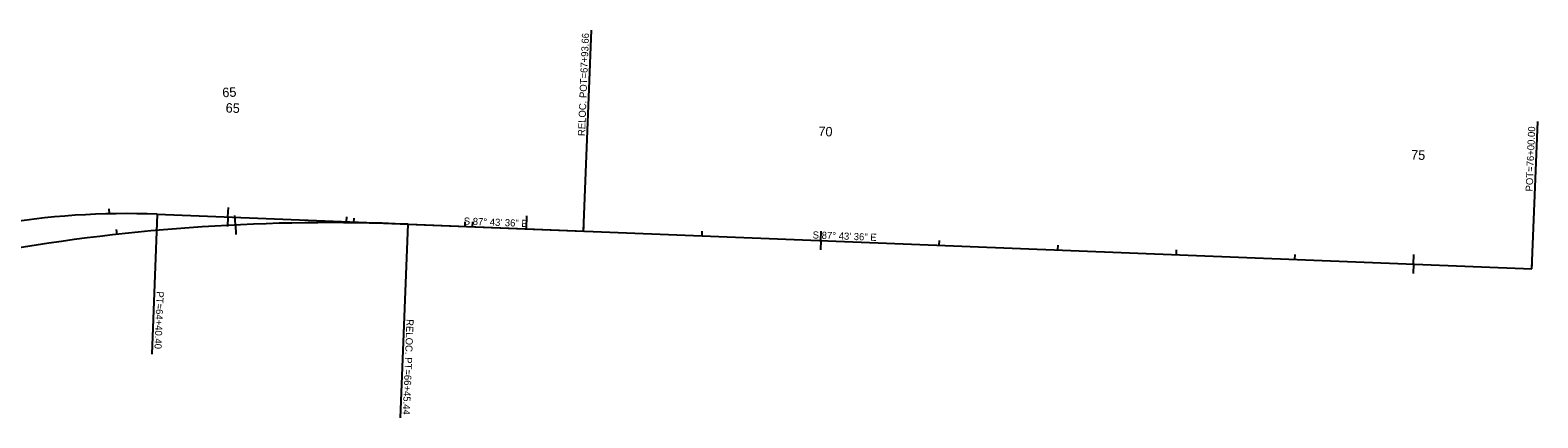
# Model space of a CAD drawing. Extents: x 1966719 to 1969284, y 1117441 to 1118086.
# Drawn here: x 1968013 to 1969284, y 1117759 to 1118086 of the extents above; entities that cross this region are included whole.
import ezdxf

# ---------------------------------------------------------------- set-up
doc = ezdxf.new("R2010")
doc.units = 0
for name, color, linetype in [('Level 1', 7, 'Continuous'), ('Level 19', 7, 'Continuous'), ('Level 21', 7, 'Continuous'), ('Level 39', 7, 'Continuous')]:
    doc.layers.add(name, color=color, linetype=linetype)

msp = doc.modelspace()

# ---------------------------------------------------------------- linework, layer by layer
at = {"layer": 'Level 1'}
for p, q in [((1969279, 1117884.9), (1969283.9, 1118009.1)), ((1968179.9, 1117928.6), (1968180.2, 1117936.6)), ((1968079.9, 1117931.3), (1968079.8, 1117935.3)), ((1968120.3, 1117930.9), (1968115.6, 1117812.9)), ((1968120.3, 1117930.9), (1969279, 1117884.9)), ((1968179.9, 1117928.6), (1968179.6, 1117920.6)), ((1968279.8, 1117924.6), (1968280, 1117928.6)), ((1968379.7, 1117920.6), (1968379.9, 1117924.6)), ((1968479.6, 1117916.7), (1968479.8, 1117920.7)), ((1968579.6, 1117912.7), (1968579.7, 1117916.7)), ((1968679.5, 1117908.7), (1968679.8, 1117916.7)), ((1968679.5, 1117908.7), (1968679.2, 1117900.8)), ((1968779.4, 1117904.8), (1968779.6, 1117908.8)), ((1968879.3, 1117900.8), (1968879.5, 1117904.8)), ((1968979.3, 1117896.8), (1968979.4, 1117900.8)), ((1969079.2, 1117892.9), (1969079.3, 1117896.9)), ((1969179.1, 1117888.9), (1969178.8, 1117880.9)), ((1969179.1, 1117888.9), (1969179.4, 1117896.9)), ((1969279, 1117884.9), (1969279.2, 1117888.9))]:
    msp.add_line(p, q, dxfattribs=at)
msp.add_arc((1968094.4, 1117277.5), 653.9, 87.7266, 111.9958, dxfattribs=at)
at = {"layer": 'Level 19'}
for p, q in [((1968186.2, 1117921.9), (1968185.8, 1117929.9)), ((1968286.1, 1117923.7), (1968286.2, 1117927.7)), ((1968386.1, 1117920.4), (1968386.2, 1117924.4)), ((1968431.5, 1117918.6), (1968431.9, 1117929.6)), ((1968086.5, 1117913.9), (1968086, 1117917.9)), ((1968186.2, 1117921.9), (1968186.5, 1117913.9)), ((1968331.5, 1117922.6), (1968479.6, 1117916.7))]:
    msp.add_line(p, q, dxfattribs=at)
msp.add_arc((1968266.6, 1116286.8), 1637, 87.7266, 111.9958, dxfattribs=at)
at = {"layer": 'Level 39'}
for p, q in [((1968479.6, 1117916.7), (1968486.4, 1118086.2)), ((1968331.5, 1117922.6), (1968325.1, 1117759.1))]:
    msp.add_line(p, q, dxfattribs=at)

# ---------------------------------------------------------------- texts
at = {"layer": 'Level 1'}
for s, rotation, p in [('POT=76+00.00', 87.7266, (1969279.6, 1117950)), ('PT=64+40.40', 267.7266, (1968119.8, 1117865.9))]:
    msp.add_text(s, height=6, rotation=rotation, dxfattribs=at).set_placement(p)
at = {"layer": 'Level 19'}
msp.add_text('65', height=8, rotation=2.8169, dxfattribs=at).set_placement((1968175.3, 1118029.5))
at = {"layer": 'Level 21'}
for s, height, p in [('65', 8, (1968177.8, 1118016.7)), ('70', 8, (1968677.4, 1117996.9)), ('75', 8, (1969177, 1117977.1)), ('S 87%%d 43\' 36" E', 6, (1968672.6, 1117910.5))]:
    msp.add_text(s, height=height, rotation=357.7266, dxfattribs=at).set_placement(p)
at = {"layer": 'Level 39'}
for s, rotation, p in [('RELOC. POT=67+93.66', 87.7266, (1968480.8, 1117996.7)), ('S 87%%d 43\' 36" E', 357.7266, (1968378.5, 1117922.2)), ('RELOC. PT=66+45.44', 267.7266, (1968330.4, 1117842.5))]:
    msp.add_text(s, height=6, rotation=rotation, dxfattribs=at).set_placement(p)

doc.saveas('drawing.dxf')
